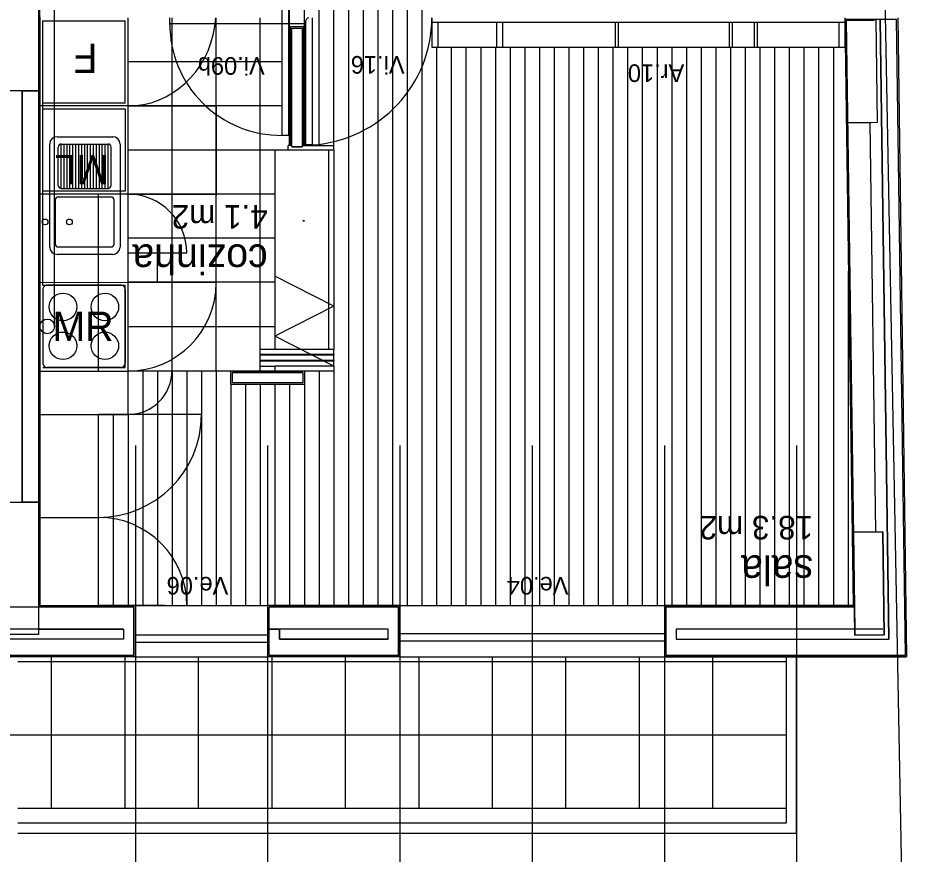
# Model space of a CAD drawing. Extents: x 1248 to 1356, y -443 to -224.
# Drawn here: x 1345.49 to 1351.55, y -248.27 to -242.57 of the extents above; entities that cross this region are included whole.
import ezdxf

# ---------------------------------------------------------------- set-up
doc = ezdxf.new("R2010")
doc.units = 0
for name, color, linetype in [('corte', 7, 'Continuous'), ('estereoctomias', 7, 'Continuous'), ('Level 1', 7, 'Continuous'), ('Level 10', 7, 'Continuous'), ('Level 11', 7, 'Continuous'), ('Level 13', 7, 'Continuous'), ('Level 2', 7, 'Continuous'), ('Level 24', 7, 'Continuous'), ('Level 3', 7, 'Continuous'), ('Level 36', 7, 'Continuous'), ('Level 4', 7, 'Continuous'), ('Level 40', 7, 'Continuous'), ('Level 60', 7, 'Continuous'), ('mob-fixo', 7, 'Continuous'), ('revestimentos', 7, 'Continuous'), ('vermelhos-cont', 7, 'Continuous'), ('vermelhos-tracej', 7, 'Continuous')]:
    doc.layers.add(name, color=color, linetype=linetype)

msp = doc.modelspace()

# ---------------------------------------------------------------- linework, layer by layer
at = {"layer": 'corte'}
for p, q in [((1346.2137, -246.734), (1344.574, -246.734)), ((1346.2137, -246.804), (1344.574, -246.804)), ((1348.0145, -246.804), (1347.2745, -246.804)), ((1346.2837, -246.914), (1344.504, -246.914))]:
    msp.add_line(p, q, dxfattribs=at)
for points in [[(1345.634, -243.0713), (1345.404, -243.0713), (1345.404, -242.1713), (1345.634, -242.1713)], [(1351.332, -242.5862), (1351.3417, -243.2861), (1351.1417, -243.2889), (1351.132, -242.589)], [(1345.404, -245.8713), (1345.634, -245.8713), (1345.634, -246.7713), (1345.404, -246.7713)], [(1351.3904, -246.7738), (1351.3806, -246.0729), (1351.1806, -246.0757), (1351.1904, -246.7766)]]:
    msp.add_lwpolyline(points, close=True, dxfattribs=at)
at = {"layer": 'estereoctomias'}
for points in [[(1349.9745, -246.734), (1349.9745, -246.804), (1351.4208, -246.804), (1351.3619, -242.5858), (1351.4719, -242.584), (1351.5324, -246.914), (1349.9045, -246.914), (1349.9045, -246.584), (1351.1877, -246.584), (1351.1898, -246.734)], [(1347.4287, -243.452), (1347.3587, -243.452), (1347.3587, -242.644), (1347.4287, -242.644)], [(1345.634, -245.8713), (1345.5237, -245.8713), (1345.5237, -243.0713), (1345.6337, -243.0713), (1345.6337, -245.8713)], [(1351.3306, -246.0736), (1351.1806, -246.0757), (1351.1417, -243.2889), (1351.2917, -243.2868)], [(1347.4337, -244.9879), (1347.4337, -245.0579), (1346.9537, -245.0579), (1346.9537, -244.9879)], [(1346.2137, -246.734), (1346.2137, -246.804), (1344.574, -246.804), (1344.574, -246.734), (1345.404, -246.734), (1345.404, -246.584), (1344.504, -246.584), (1344.504, -246.914), (1346.2837, -246.914), (1346.2837, -246.584), (1345.634, -246.584), (1345.634, -246.734)], [(1348.0845, -246.584), (1348.0845, -246.914), (1347.2045, -246.914), (1347.2045, -246.734), (1347.2745, -246.734), (1347.2745, -246.804), (1348.0145, -246.804), (1348.0145, -246.734), (1347.2045, -246.734), (1347.2045, -246.584)], [(1348.0845, -246.584), (1348.0845, -246.914), (1347.2045, -246.914), (1347.2045, -246.734), (1347.2745, -246.734), (1347.2745, -246.804), (1348.0145, -246.804), (1348.0145, -246.734), (1347.2045, -246.734), (1347.2045, -246.584)]]:
    msp.add_lwpolyline(points, close=True, dxfattribs=at)
at = {"layer": 'Level 1'}
for p, q in [((1345.6337, -242.484), (1345.6337, -246.574)), ((1351.132, -242.589), (1351.1877, -246.584)), ((1351.3619, -242.5858), (1351.4208, -246.804)), ((1351.4719, -242.584), (1351.5324, -246.914)), ((1347.3587, -243.452), (1347.3587, -242.644)), ((1347.3587, -242.644), (1347.4287, -242.644)), ((1347.4287, -242.644), (1347.4287, -243.452)), ((1345.5237, -243.0713), (1345.5237, -245.8713)), ((1351.2917, -243.2868), (1351.3306, -246.0736)), ((1347.3337, -243.474), (1347.3337, -243.442)), ((1347.3587, -243.442), (1347.3337, -243.442)), ((1347.3587, -243.452), (1347.4287, -243.452)), ((1347.4287, -243.442), (1347.6437, -243.442)), ((1347.6437, -243.474), (1347.6437, -243.442)), ((1347.6437, -243.474), (1347.3337, -243.474)), ((1347.4437, -244.9779), (1346.9437, -244.9779)), ((1346.9437, -245.0679), (1346.9437, -244.9779)), ((1347.6437, -244.9459), (1347.2437, -244.9459)), ((1347.2437, -244.9459), (1347.2437, -244.9779)), ((1347.6437, -244.9779), (1347.4437, -244.9779)), ((1347.4437, -244.9779), (1347.4437, -245.0679)), ((1347.6437, -244.9459), (1347.6437, -244.9779)), ((1346.9537, -245.0579), (1346.9537, -244.9879)), ((1347.4337, -244.9879), (1346.9537, -244.9879)), ((1347.4337, -244.9879), (1347.4337, -245.0579)), ((1346.9437, -245.0679), (1347.4437, -245.0679)), ((1347.4337, -245.0579), (1346.9537, -245.0579)), ((1344.504, -246.584), (1346.2837, -246.584)), ((1346.2837, -246.584), (1346.2837, -246.914)), ((1348.0845, -246.584), (1347.2045, -246.584)), ((1347.2045, -246.914), (1347.2045, -246.584)), ((1348.0845, -246.914), (1348.0845, -246.584)), ((1351.1877, -246.584), (1349.9045, -246.584)), ((1349.9045, -246.584), (1349.9045, -246.914)), ((1346.2137, -246.734), (1346.2137, -246.804)), ((1348.0145, -246.734), (1347.2745, -246.734)), ((1347.2745, -246.804), (1347.2745, -246.734)), ((1348.0145, -246.804), (1348.0145, -246.734)), ((1351.3804, -246.734), (1349.9745, -246.734)), ((1349.9745, -246.734), (1349.9745, -246.804)), ((1349.9745, -246.804), (1351.4208, -246.804)), ((1348.0845, -246.914), (1347.2045, -246.914)), ((1349.9045, -246.914), (1351.5324, -246.914))]:
    msp.add_line(p, q, dxfattribs=at)
for points in [[(1351.1218, -242.584), (1351.4719, -242.584)], [(1351.132, -242.589), (1351.322, -242.589)]]:
    msp.add_lwpolyline(points, dxfattribs=at)
at = {"layer": 'Level 10'}
for p, q in [((1347.3437, -243.442), (1347.3437, -240.974)), ((1347.9437, -240.974), (1347.9437, -246.574)), ((1348.0437, -240.974), (1348.0437, -246.574)), ((1348.1437, -240.974), (1348.1437, -246.574)), ((1348.2437, -240.974), (1348.2437, -246.574)), ((1347.4437, -243.442), (1347.4437, -240.989)), ((1347.5437, -243.442), (1347.5437, -240.989)), ((1347.6437, -243.442), (1347.6437, -240.989)), ((1347.7437, -240.989), (1347.7437, -246.574)), ((1347.8437, -240.989), (1347.8437, -246.574)), ((1346.5437, -244.9779), (1346.5437, -242.574)), ((1346.8437, -244.9779), (1346.8437, -242.574)), ((1347.1437, -244.9779), (1347.1437, -242.574)), ((1348.3437, -242.774), (1348.3437, -246.574)), ((1348.4437, -242.774), (1348.4437, -246.574)), ((1348.5437, -242.774), (1348.5437, -246.574)), ((1348.6437, -242.774), (1348.6437, -246.574)), ((1348.7437, -242.774), (1348.7437, -246.574)), ((1348.8437, -242.774), (1348.8437, -246.574)), ((1348.9437, -242.774), (1348.9437, -246.574)), ((1349.0437, -242.774), (1349.0437, -246.574)), ((1349.1437, -242.774), (1349.1437, -246.574)), ((1349.2437, -242.774), (1349.2437, -246.574)), ((1349.3437, -242.774), (1349.3437, -246.574)), ((1349.4437, -242.774), (1349.4437, -246.574)), ((1349.5437, -242.774), (1349.5437, -246.574)), ((1349.6437, -242.774), (1349.6437, -246.574)), ((1349.7437, -242.774), (1349.7437, -246.574)), ((1349.8437, -242.774), (1349.8437, -246.574)), ((1349.9437, -242.774), (1349.9437, -246.574)), ((1350.0437, -242.774), (1350.0437, -246.574)), ((1350.1437, -242.774), (1350.1437, -246.574)), ((1350.2437, -242.774), (1350.2437, -246.574)), ((1350.3437, -242.774), (1350.3437, -246.574)), ((1350.4437, -242.774), (1350.4437, -246.574)), ((1350.5437, -242.774), (1350.5437, -246.574)), ((1350.6437, -242.774), (1350.6437, -246.574)), ((1350.7437, -242.774), (1350.7437, -246.574)), ((1350.8437, -242.774), (1350.8437, -246.574)), ((1350.9437, -242.774), (1350.9437, -246.574)), ((1351.0437, -242.774), (1351.0437, -246.574)), ((1347.2937, -242.874), (1346.2437, -242.874)), ((1347.2937, -243.174), (1346.2437, -243.174)), ((1347.2437, -243.474), (1346.2437, -243.474)), ((1347.2437, -243.774), (1346.2437, -243.774)), ((1347.2437, -244.074), (1346.2437, -244.074)), ((1351.1437, -244.2989), (1351.1437, -246.574)), ((1347.2437, -244.374), (1346.2437, -244.374)), ((1347.2437, -244.6779), (1346.2437, -244.6779)), ((1346.9437, -244.9779), (1346.2437, -244.9779)), ((1346.3437, -244.9779), (1346.3437, -246.574)), ((1346.4437, -244.9779), (1346.4437, -246.574)), ((1346.5437, -244.9779), (1346.5437, -246.574)), ((1346.6437, -244.9779), (1346.6437, -246.574)), ((1346.7437, -244.9779), (1346.7437, -246.574)), ((1346.8437, -244.9779), (1346.8437, -246.574)), ((1347.5437, -244.9779), (1347.5437, -246.574)), ((1347.6437, -244.9779), (1347.6437, -246.574)), ((1346.9437, -245.0679), (1346.9437, -246.574)), ((1347.0437, -245.0679), (1347.0437, -246.574)), ((1347.1437, -245.0679), (1347.1437, -246.574)), ((1347.2437, -245.0679), (1347.2437, -246.574)), ((1347.3437, -245.0679), (1347.3437, -246.574)), ((1347.4437, -245.0679), (1347.4437, -246.574)), ((1346.1437, -245.274), (1346.1437, -246.574)), ((1346.2437, -245.274), (1346.2437, -246.574)), ((1345.494, -246.954), (1350.724, -246.954)), ((1345.724, -247.954), (1345.724, -246.924)), ((1346.224, -247.954), (1346.224, -246.924)), ((1346.724, -247.954), (1346.724, -246.924)), ((1347.224, -247.954), (1347.224, -246.924)), ((1347.724, -247.954), (1347.724, -246.924)), ((1348.224, -247.954), (1348.224, -246.924)), ((1348.724, -247.954), (1348.724, -246.924)), ((1349.224, -247.954), (1349.224, -246.924)), ((1349.724, -247.954), (1349.724, -246.924)), ((1350.224, -247.954), (1350.224, -246.924)), ((1340.0933, -247.454), (1350.724, -247.454)), ((1345.494, -247.954), (1350.724, -247.954))]:
    msp.add_line(p, q, dxfattribs=at)
at = {"layer": 'Level 11'}
for p, q in [((1345.6637, -243.154), (1345.6637, -242.594)), ((1345.6637, -242.594), (1346.2237, -242.594)), ((1346.2237, -243.154), (1346.2237, -242.594)), ((1346.2237, -243.154), (1345.6637, -243.154)), ((1345.7688, -243.7151), (1345.7688, -243.4536)), ((1345.7888, -243.4336), (1346.1088, -243.4336)), ((1345.7888, -243.7351), (1345.7888, -243.4336)), ((1345.8088, -243.7351), (1345.8088, -243.4336)), ((1345.8288, -243.7351), (1345.8288, -243.4336)), ((1345.8488, -243.7351), (1345.8488, -243.4336)), ((1345.8688, -243.7351), (1345.8688, -243.4336)), ((1345.8888, -243.7351), (1345.8888, -243.4336)), ((1345.9088, -243.7351), (1345.9088, -243.4336)), ((1345.9288, -243.7351), (1345.9288, -243.4336)), ((1345.9488, -243.7351), (1345.9488, -243.4336)), ((1345.9688, -243.7351), (1345.9688, -243.4336)), ((1345.9888, -243.7351), (1345.9888, -243.4336)), ((1346.0088, -243.7351), (1346.0088, -243.4336)), ((1346.0288, -243.7351), (1346.0288, -243.4336)), ((1346.0488, -243.7351), (1346.0488, -243.4336)), ((1346.0688, -243.7351), (1346.0688, -243.4336)), ((1346.0888, -243.7351), (1346.0888, -243.4336)), ((1346.1088, -243.7351), (1346.1088, -243.4336)), ((1346.1288, -243.7151), (1346.1288, -243.4536)), ((1345.7888, -243.7351), (1346.1088, -243.7351)), ((1345.7488, -243.8136), (1345.7488, -244.1136)), ((1346.1288, -243.7936), (1345.7688, -243.7936)), ((1346.1488, -244.1136), (1346.1488, -243.8136)), ((1345.7688, -244.1336), (1346.1288, -244.1336)), ((1345.6638, -244.424), (1345.6638, -244.924)), ((1346.1938, -244.394), (1345.6938, -244.394)), ((1346.2238, -244.424), (1346.2238, -244.924)), ((1346.1938, -244.954), (1345.6938, -244.954))]:
    msp.add_line(p, q, dxfattribs=at)
for points in [[(1345.761, -243.3833), (1346.1394, -243.3833)], [(1345.711, -244.1347), (1345.711, -243.4333)], [(1346.1894, -243.4333), (1346.1894, -244.1347)], [(1346.1394, -244.1847), (1345.761, -244.1847)]]:
    msp.add_lwpolyline(points, dxfattribs=at)
for centre, radius in [((1345.6789, -243.9635), 0.0199), ((1345.8448, -243.9635), 0.0199), ((1345.8012, -244.5419), 0.0936), ((1346.0864, -244.5419), 0.0936), ((1345.8012, -244.8061), 0.0936), ((1346.0864, -244.8061), 0.0936)]:
    msp.add_circle(centre, radius, dxfattribs=at)
for centre, radius, start, end in [((1345.761, -243.4333), 0.05, 90, 180), ((1346.1394, -243.4333), 0.05, 0, 90), ((1345.7888, -243.4535), 0.02, 90, 180), ((1346.1088, -243.4535), 0.02, 0, 90), ((1345.7888, -243.7151), 0.02, 180, 270), ((1346.1088, -243.7151), 0.02, 270, 0), ((1345.7688, -243.8135), 0.02, 90, 180), ((1346.1288, -243.8135), 0.02, 0, 90), ((1345.7688, -244.1135), 0.02, 180, 270), ((1346.1288, -244.1135), 0.02, 270, 0), ((1345.761, -244.1347), 0.05, 180, 270), ((1346.1394, -244.1347), 0.05, 270, 0), ((1345.6938, -244.424), 0.03, 89.99985, 180.0002), ((1346.1938, -244.424), 0.03, 0.00009, 90.0001), ((1345.6938, -244.924), 0.03, 180.00021, 269.99999), ((1346.1938, -244.924), 0.03, 270.00005, 0.00002)]:
    msp.add_arc(centre, radius, start, end, dxfattribs=at)
at = {"layer": 'Level 13'}
for p, q in [((1347.2937, -243.374), (1347.2937, -242.469)), ((1347.3387, -243.374), (1347.3387, -242.469)), ((1346.2437, -245.274), (1346.2437, -242.574)), ((1347.4437, -242.619), (1347.4437, -242.574)), ((1347.4537, -243.4395), (1347.4537, -242.594)), ((1347.4987, -243.4395), (1347.4987, -242.574)), ((1348.3117, -242.574), (1348.3117, -242.774)), ((1348.3117, -242.604), (1351.1218, -242.604)), ((1348.3517, -242.604), (1348.3517, -242.774)), ((1348.7517, -242.604), (1348.7517, -242.774)), ((1348.7917, -242.604), (1348.7917, -242.774)), ((1349.5584, -242.604), (1349.5584, -242.774)), ((1349.5784, -242.604), (1349.5784, -242.774)), ((1350.3351, -242.604), (1350.3351, -242.774)), ((1350.3551, -242.604), (1350.3551, -242.774)), ((1350.5051, -242.604), (1350.5051, -242.774)), ((1350.5251, -242.604), (1350.5251, -242.774)), ((1351.0818, -242.604), (1351.0818, -242.774)), ((1351.1218, -242.604), (1351.1218, -242.774)), ((1348.3117, -242.774), (1351.1245, -242.774)), ((1346.2437, -243.174), (1345.6437, -243.174)), ((1347.3387, -243.374), (1347.2937, -243.374)), ((1347.4987, -243.4395), (1347.4537, -243.4395)), ((1347.6437, -244.8309), (1347.1437, -244.8309)), ((1347.1437, -244.8659), (1347.1437, -244.8309)), ((1347.6437, -244.8659), (1347.6437, -244.8309)), ((1347.6437, -244.8659), (1347.1437, -244.8659)), ((1347.6437, -244.8709), (1347.1437, -244.8709)), ((1347.1437, -244.9059), (1347.1437, -244.8709)), ((1347.6437, -244.9059), (1347.1437, -244.9059)), ((1347.6437, -244.9109), (1347.1437, -244.9109)), ((1347.1437, -244.9459), (1347.1437, -244.9109)), ((1347.6437, -244.9059), (1347.6437, -244.8709)), ((1347.6437, -244.9459), (1347.6437, -244.9109)), ((1347.1437, -244.9459), (1347.2437, -244.9459)), ((1345.6437, -245.274), (1346.2437, -245.274)), ((1346.0437, -246.574), (1346.0437, -245.274))]:
    msp.add_line(p, q, dxfattribs=at)
msp.add_arc((1347.4737, -242.594), 0.02, 90, 180, dxfattribs=at)
at = {"layer": 'Level 2'}
for p, q in [((1347.2437, -243.474), (1347.2437, -244.8309)), ((1347.3437, -243.474), (1347.2437, -243.474)), ((1347.6437, -243.474), (1347.6437, -244.8309)), ((1347.1437, -244.8659), (1347.1437, -244.8709)), ((1347.1437, -244.9059), (1347.1437, -244.9109)), ((1347.6437, -244.8659), (1347.6437, -244.8709)), ((1347.6437, -244.9059), (1347.6437, -244.9109)), ((1346.2937, -246.574), (1347.1945, -246.574)), ((1348.0945, -246.574), (1349.8945, -246.574)), ((1346.2937, -246.774), (1347.1945, -246.774)), ((1348.0945, -246.764), (1349.8945, -246.764)), ((1346.2937, -246.824), (1347.1945, -246.824)), ((1348.0945, -246.814), (1349.8945, -246.814)), ((1346.2937, -246.924), (1347.1945, -246.924)), ((1348.0945, -246.924), (1349.8945, -246.924)), ((1350.724, -248.054), (1350.724, -246.924)), ((1350.794, -248.124), (1350.794, -246.924)), ((1345.494, -248.054), (1350.724, -248.054)), ((1345.494, -248.124), (1350.794, -248.124))]:
    msp.add_line(p, q, dxfattribs=at)
at = {"layer": 'Level 24'}
msp.add_lwpolyline([(1351.1904, -246.7766), (1351.1806, -246.0757), (1351.3806, -246.0729), (1351.3904, -246.7738)], close=True, dxfattribs=at)
msp.add_lwpolyline([(1351.1904, -246.7766), (1351.1806, -246.0757), (1351.3806, -246.0729), (1351.3904, -246.7738)], close=True, dxfattribs=at)
at = {"layer": 'Level 3'}
for p, q in [((1346.2437, -243.774), (1345.6437, -243.774)), ((1346.0437, -244.974), (1346.0437, -243.774)), ((1346.0437, -244.9779), (1346.2437, -244.9779)), ((1345.6437, -245.974), (1346.0437, -245.974))]:
    msp.add_line(p, q, dxfattribs=at)
at = {"layer": 'Level 36'}
for p, q in [((1347.4337, -243.954), (1347.4437, -243.954)), ((1347.4337, -243.956), (1347.4437, -243.956))]:
    msp.add_line(p, q, dxfattribs=at)
at = {"layer": 'Level 4'}
for p, q in [((1347.4437, -242.614), (1346.5286, -242.614)), ((1346.5287, -242.619), (1346.5287, -242.574)), ((1347.4437, -242.619), (1347.4437, -242.574)), ((1345.6637, -244.394), (1345.6637, -243.154)), ((1345.6637, -243.194), (1346.2237, -243.194)), ((1346.2237, -243.194), (1346.2237, -243.754)), ((1346.2437, -243.174), (1346.8437, -243.174)), ((1346.2437, -243.174), (1346.8437, -243.174)), ((1346.8437, -243.174), (1346.8437, -243.784)), ((1347.6087, -243.474), (1347.6087, -244.8309)), ((1346.2237, -243.754), (1345.6637, -243.754)), ((1346.2437, -243.774), (1346.8437, -243.774)), ((1346.2437, -244.174), (1346.6437, -244.174)), ((1346.4437, -244.374), (1346.4437, -244.174)), ((1347.6437, -244.5374), (1347.2437, -244.3331)), ((1345.6437, -244.374), (1346.2437, -244.3763)), ((1345.6637, -244.394), (1346.2237, -244.394)), ((1346.2237, -244.954), (1346.2237, -244.394)), ((1346.2437, -244.374), (1346.8437, -244.374)), ((1347.6437, -244.5374), (1347.2437, -244.7416)), ((1347.6437, -244.9459), (1347.2437, -244.7416)), ((1345.6437, -244.9779), (1346.2437, -244.9779)), ((1345.6637, -244.954), (1346.2237, -244.954)), ((1346.5437, -244.9779), (1346.2437, -244.9779)), ((1346.7437, -245.274), (1346.0437, -245.274)), ((1346.0437, -246.572), (1346.4937, -246.572))]:
    msp.add_line(p, q, dxfattribs=at)
for centre, radius, start, end in [((1346.2437, -244.174), 0.4, 0, 90), ((1346.2437, -244.3779), 0.6, 270, 0), ((1346.2437, -244.974), 0.3, 270, 0), ((1346.0437, -246.574), 0.6, 0, 90)]:
    msp.add_arc(centre, radius, start, end, dxfattribs=at)
for centre, major_axis, ratio, start_param, end_param in [((1346.2437, -242.524), (0, -0.6502), 0.922835, 0.083434, 1.493818), ((1347.2876, -242.62), (0.7591, 0), 0.993555, 3.133653, 4.720415), ((1347.4329, -242.574), (-0.8788, 0), 0.987656, 1.645722, 3.141593), ((1346.0437, -245.274), (0, -0.7), 0.999989, 0, 1.570796)]:
    msp.add_ellipse(centre, major_axis=major_axis, ratio=ratio, start_param=start_param, end_param=end_param, dxfattribs=at)
at = {"layer": 'mob-fixo'}
for p, q in [((1345.6437, -244.674), (1345.6437, -240.884)), ((1345.7437, -244.674), (1345.7437, -240.884))]:
    msp.add_line(p, q, dxfattribs=at)
msp.add_circle((1345.6937, -244.674), 0.05, dxfattribs=at)
at = {"layer": 'revestimentos'}
for p, q in [((1345.6437, -242.569), (1345.6437, -246.574)), ((1351.1218, -242.574), (1351.1776, -246.574)), ((1351.4818, -242.574), (1351.5425, -246.924)), ((1347.3487, -242.634), (1347.4387, -242.634)), ((1347.3487, -243.442), (1347.3487, -242.634)), ((1347.4387, -242.634), (1347.4387, -243.442)), ((1345.6437, -246.574), (1346.2937, -246.574)), ((1346.2937, -246.574), (1346.2937, -246.924)), ((1347.1945, -246.924), (1347.1945, -246.574)), ((1348.0945, -246.574), (1347.1945, -246.574)), ((1348.0945, -246.924), (1348.0945, -246.574)), ((1349.8945, -246.574), (1349.8945, -246.924)), ((1351.1776, -246.574), (1349.8945, -246.574)), ((1346.2937, -246.924), (1344.494, -246.924)), ((1348.0945, -246.924), (1347.1945, -246.924)), ((1349.8945, -246.924), (1351.5425, -246.924))]:
    msp.add_line(p, q, dxfattribs=at)
at = {"layer": 'vermelhos-cont'}
msp.add_line((1351.1483, -229.6198), (1351.553, -250.7923), dxfattribs=at)
at = {"layer": 'vermelhos-tracej'}
for p, q in [((1346.294, -245.4838), (1346.294, -250.4459)), ((1347.194, -245.4838), (1347.194, -250.4459)), ((1348.094, -245.4838), (1348.094, -250.4459)), ((1348.994, -245.4838), (1348.994, -250.4459)), ((1349.894, -245.4838), (1349.894, -250.4459)), ((1350.794, -245.4838), (1350.794, -250.4459))]:
    msp.add_line(p, q, dxfattribs=at)

# ---------------------------------------------------------------- texts
at = {"layer": 'Level 11'}
for s, p in [('F', (1346.0369, -242.749)), ('ML', (1346.1154, -243.5071))]:
    msp.add_text(s, height=0.2, rotation=180, dxfattribs=at).set_placement(p)
msp.add_text('MR', height=0.2, dxfattribs=at).set_placement((1345.73, -244.774))
at = {"layer": 'Level 40'}
for s, p in [('Vi.09b', (1347.174, -242.8414)), ('Vi.16', (1348.1258, -242.8341)), ('Ar.10', (1350.0289, -242.8906)), ('Ve.06', (1346.9261, -246.3793)), ('Ve.04', (1349.2408, -246.3793))]:
    msp.add_text(s, height=0.12, rotation=180.00001, dxfattribs=at).set_placement(p)
at = {"layer": 'Level 60'}
for s, height, p in [('4.1 m2', 0.16, (1347.1947, -243.8484)), ('cozinha', 0.2, (1347.1947, -244.1162)), ('18.3 m2', 0.16, (1350.906, -245.9642)), ('sala', 0.2, (1350.906, -246.232))]:
    msp.add_text(s, height=height, rotation=180, dxfattribs=at).set_placement(p)

doc.saveas('drawing.dxf')
